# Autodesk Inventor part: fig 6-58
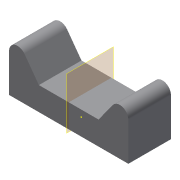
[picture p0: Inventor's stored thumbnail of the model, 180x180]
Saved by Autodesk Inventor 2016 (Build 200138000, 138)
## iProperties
Created: 2011-07
Part Number: fig 6-58
Material: Generic
Document SubType Name: Modeling
Designer: CadCim
Density: 1 g/cm^3
Appearance: Default
Author: CadCim
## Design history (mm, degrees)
sketch "Sketch1"
  geometry: 1 further point
sketch "Sketch2"
  geometry: L1 (3, -4)-(17, -4); L2 (17, -4)-(17, 7); L3 (17, 7)-(14, 7); L4 (14, 7)-(10, 1.5); L5 (10, 1.5)-(3, 1.5); L6 (3, -4)-(-11, -4); L7 (-11, -4)-(-11, 7); L8 (-11, 7)-(-8, 7); L9 (-8, 7)-(-4, 1.5); L10 (-4, 1.5)-(3, 1.5); 1 further point
  constraints: 20 end point, 2 parallel, 1 perpendicular
extrude "Extrusion1" new body sketch "Sketch2" distance "d0" = 10; taper "d1" = 0 deg
fillet "Fillet1" dims "d2" = 2
workplane "Work Plane1"
mirror "Mirror1"
body "Solid1"
